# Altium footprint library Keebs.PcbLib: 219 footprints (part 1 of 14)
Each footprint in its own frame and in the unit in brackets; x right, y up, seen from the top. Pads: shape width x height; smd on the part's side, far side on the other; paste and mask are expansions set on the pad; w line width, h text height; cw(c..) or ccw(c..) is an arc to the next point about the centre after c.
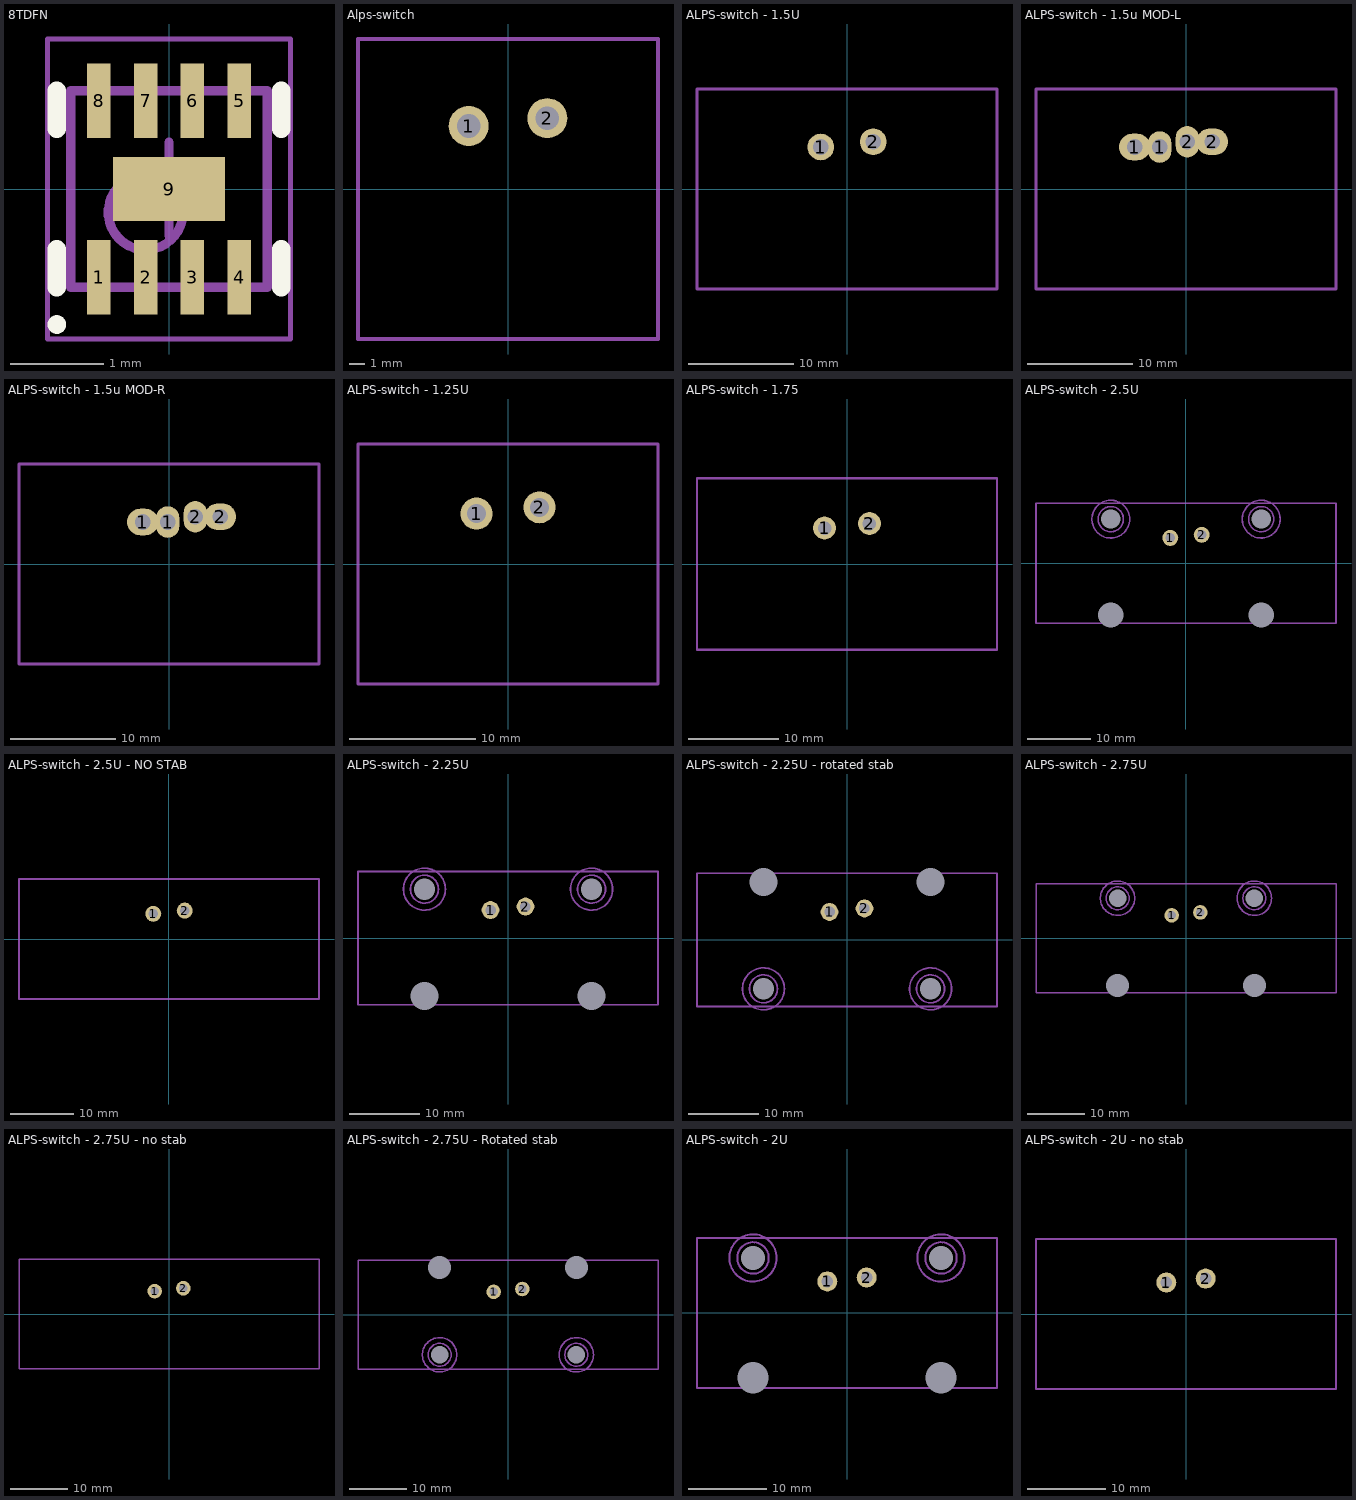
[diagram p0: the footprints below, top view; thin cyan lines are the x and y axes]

## 8TDFN [mm] "Generated for the MAX17048G+T10"
height 0.8
pads (9):
  rect 0.25x0.8 smd: 1(-0.75,-0.945) 2(-0.25,-0.945) 3(0.25,-0.945) 4(0.75,-0.945) 5(0.75,0.945) 6(0.25,0.945) 7(-0.25,0.945) 8(-0.75,0.945)
  rect 1.2x0.69 smd: 9(0,0)
Top Overlay:
  circle w0.1: c-1.2,-1.45 r0.05
  lines w0.2: -1.2,-1.05 -1.2,-0.645 ; -1.2,0.645 -1.2,1.05 ; 1.2,-1.05 1.2,-0.645 ; 1.2,0.645 1.2,1.05
Mechanical 13:
  circle w0.1: c-0.25,-0.25 r0.4
  lines w0.1: -1.05,-1.05 -1.05,1.05 1.05,1.05 1.05,-1.05 -1.05,-1.05
  text ".Designator" at 0.711,0.051 h0.3
Mechanical 15:
  lines w0.05: -1.3,-1.605 -1.3,1.605 1.3,1.605 1.3,-1.605 -1.3,-1.605
  lines w0.1: -0.5,0 0.5,0 ; 0,-0.5 0,0.5
3D body "8TDFN.step": height 0.8, standoff 0, extent -1.05,-1.1 1.05,1.1

## Alps-switch [mm]
pads (3):
  round 2.54 hole 1.5 mask-0.5: 1(-2.5,4) 2(2.5,4.5)
  round 1 on Mech13: ""(0,0)
Mechanical 13:
  lines w0.254: -9.525,-9.525 -9.525,9.525 9.525,9.525 9.525,-9.525 -9.525,-9.525
  text ".Designator" at -3.575,-3.7 h0.7

## ALPS-switch - 1.5U [mm]
pads (3):
  round 2.54 hole 1.5 mask-0.5: 1(-2.5,4) 2(2.5,4.5)
  round 1 on Mech13: ""(0,0)
Mechanical 13:
  lines w0.254: -14.287,-9.525 14.287,-9.525 14.287,9.525 -14.287,9.525 -14.287,-9.525
  text ".Designator" at -3.825,-3.375 h0.7

## ALPS-switch - 1.5u MOD-L [mm]
pads (6):
  oval 3x2.54 hole 1.5 mask-0.7: 1(-4.881,4) 2(2.5,4.5)
  oval 2.2x3 hole 1.5 mask-0.7: 1(-2.5,4) 2(0.119,4.5)
  round 1 on Mech13: ""(-2.381,0) ""(0,0)
Mechanical 13:
  lines w0.254: -14.287,-9.525 -14.287,9.525 14.287,9.525 14.287,-9.525 -14.287,-9.525
  text ".Designator" at 2.9,2.625 h0.7

## ALPS-switch - 1.5u MOD-R [mm]
pads (6):
  oval 3x2.54 hole 1.5 mask-0.7: 1(-2.5,4) 2(4.881,4.5)
  oval 2.2x3 hole 1.5 mask-0.7: 1(-0.119,4) 2(2.5,4.5)
  round 1 on Mech13: ""(0,0) ""(2.381,0)
Mechanical 13:
  lines w0.254: -14.287,-9.525 -14.287,9.525 14.287,9.525 14.287,-9.525 -14.287,-9.525
  text ".Designator" at -10.675,-5.325 h0.7

## ALPS-switch - 1.25U [mm]
pads (3):
  round 2.54 hole 1.5 mask-0.5: 1(-2.5,4) 2(2.5,4.5)
  round 1 on Mech13: ""(0,0)
Mechanical 13:
  lines w0.254: -11.906,-9.525 11.906,-9.525 11.906,9.525 -11.906,9.525 -11.906,-9.525
  text ".Designator" at -3.425,-3.425 h0.7

## ALPS-switch - 1.75 [mm]
pads (3):
  round 2.54 hole 1.5 mask-0.5: 1(-2.5,4) 2(2.5,4.5)
  round 1 on Mech13: ""(0,0)
Mechanical 13:
  lines w0.254: -16.669,-9.525 -16.669,9.525 16.669,9.525 16.669,-9.525 -16.669,-9.525
  text ".Designator" at -3.825,-3.375 h0.7

## ALPS-switch - 2.5U [mil]
pads (7):
  round 100 hole 59.06 mask-19.68: 1(-98.43,157.48) 2(98.43,177.17)
  round 60 hole 157.48 unplated: ""(-470,-325) ""(470,-325)
  round 60 hole 120 unplated: ""(-470,275) ""(470,275)
  round 39.37 on Mech13: ""(0,0)
Mechanical 13:
  lines w10: -937.48,-375 -937.48,375 937.48,375 937.5,-375 -937.48,-375
  text ".Designator" at -150.59,-132.87 h27.56
Mechanical 15:
  circle w10: c470,275 r78.74
  circle w10: c470,275 r118.11
  circle w10: c-470,275 r78.74
  circle w10: c-470,275 r118.11

## ALPS-switch - 2.5U - NO STAB [mm]
pads (3):
  round 2.54 hole 1.5 mask-0.5: 1(-2.5,4) 2(2.5,4.5)
  round 1 on Mech13: ""(0,0)
Mechanical 13:
  lines w0.254: -23.812,-9.525 -23.812,9.525 23.812,9.525 23.812,-9.525 -23.812,-9.525
  text ".Designator" at -3.825,-3.375 h0.7

## ALPS-switch - 2.25U [mil]
pads (7):
  round 100 hole 59.06 mask-19.68: 1(-98.43,157.48) 2(98.43,177.17)
  round 60 hole 157.48 unplated: ""(-470,-325) ""(470,-325)
  round 60 hole 120 unplated: ""(-470,275) ""(470,275)
  round 39.37 on Mech13: ""(0,0)
Mechanical 13:
  lines w10: -843.75,-375 -843.75,375 843.75,375 843.75,-375 -843.75,-375
  text ".Designator" at -150.59,-132.87 h27.56
Mechanical 15:
  circle w10: c470,275 r78.74
  circle w10: c470,275 r118.11
  circle w10: c-470,275 r78.74
  circle w10: c-470,275 r118.11

## ALPS-switch - 2.25U - rotated stab [mil]
pads (7):
  round 100 hole 59.06 mask-19.68: 1(-98.43,157.48) 2(98.43,177.17)
  round 60 hole 120 unplated: ""(-470,-275) ""(470,-275)
  round 60 hole 157.48 unplated: ""(-470,325) ""(470,325)
  round 39.37 on Mech13: ""(0,0)
Mechanical 13:
  lines w10: -843.75,-375 843.75,-375 843.75,375 -843.75,375 -843.75,-375
  text ".Designator" at -150.59,-132.87 h27.56
Mechanical 15:
  circle w10: c-470,-275 r118.11
  circle w10: c-470,-275 r78.74
  circle w10: c470,-275 r118.11
  circle w10: c470,-275 r78.74

## ALPS-switch - 2.75U [mil]
pads (7):
  round 100 hole 59.06 mask-19.68: 1(-98.43,157.48) 2(98.43,177.17)
  round 60 hole 157.48 unplated: ""(-470,-325) ""(470,-325)
  round 60 hole 120 unplated: ""(-470,275) ""(470,275)
  round 39.37 on Mech13: ""(0,0)
Mechanical 13:
  lines w10: -1031.25,-375 1031.25,-375 1031.25,375 -1031.25,375 -1031.25,-375
  text ".Designator" at -150.59,-132.87 h27.56
Mechanical 15:
  circle w10: c-470,275 r118.11
  circle w10: c-470,275 r78.74
  circle w10: c470,275 r118.11
  circle w10: c470,275 r78.74

## ALPS-switch - 2.75U - no stab [mm]
pads (3):
  round 2.54 hole 1.5 mask-0.5: 1(-2.5,4) 2(2.5,4.5)
  round 1 on Mech13: ""(0,0)
Mechanical 13:
  lines w0.254: -26.194,-9.525 -26.194,9.525 26.194,9.525 26.194,-9.525 -26.194,-9.525
  text ".Designator" at -3.825,-3.375 h0.7

## ALPS-switch - 2.75U - Rotated stab [mil]
pads (7):
  round 100 hole 59.06 mask-19.68: 1(-98.43,157.48) 2(98.43,177.17)
  round 60 hole 120 unplated: ""(-470,-275) ""(470,-275)
  round 60 hole 157.48 unplated: ""(-470,325) ""(470,325)
  round 39.37 on Mech13: ""(0,0)
Mechanical 13:
  lines w10: -1031.25,-375 1031.25,-375 1031.25,375 -1031.25,375 -1031.25,-375
  text ".Designator" at -150.59,-132.87 h27.56
Mechanical 15:
  circle w10: c470,-275 r118.11
  circle w10: c470,-275 r78.74
  circle w10: c-470,-275 r118.11
  circle w10: c-470,-275 r78.74

## ALPS-switch - 2U [mil]
pads (7):
  round 100 hole 59.06 mask-19.68: 1(-98.43,157.48) 2(98.43,177.17)
  round 60 hole 157.48 unplated: ""(-470,-325) ""(470,-325)
  round 60 hole 120 unplated: ""(-470,275) ""(470,275)
  round 39.37 on Mech13: ""(0,0)
Mechanical 13:
  lines w10: -750,-375 750,-375 750,375 -750,375 -750,-375
  text ".Designator" at -150.59,-132.87 h27.56
Mechanical 15:
  circle w10: c-470,275 r118.11
  circle w10: c-470,275 r78.74
  circle w10: c470,275 r118.11
  circle w10: c470,275 r78.74

## ALPS-switch - 2U - no stab [mm]
pads (3):
  round 2.54 hole 1.5 mask-0.5: 1(-2.5,4) 2(2.5,4.5)
  round 1 on Mech13: ""(0,0)
Mechanical 13:
  lines w0.254: -19.05,-9.525 -19.05,9.525 19.05,9.525 19.05,-9.525 -19.05,-9.525
  text ".Designator" at -3.825,-3.375 h0.7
